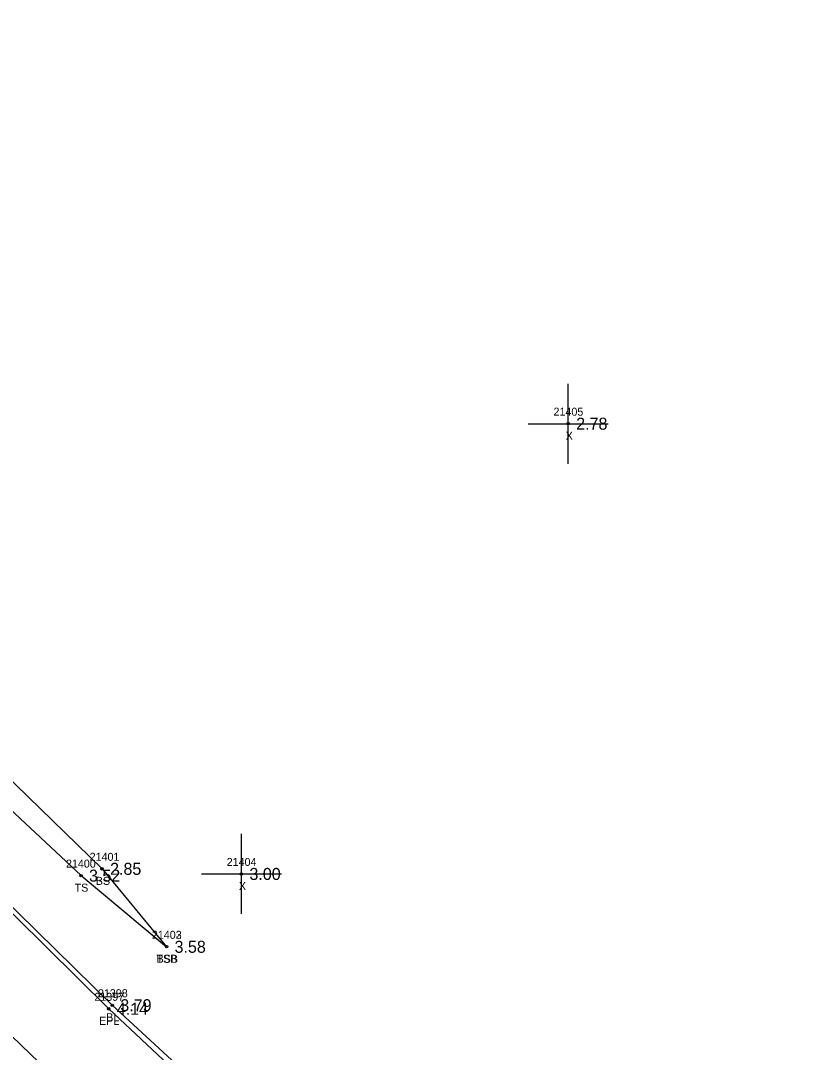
# Model space of a CAD drawing. Extents: x 2608745 to 2610333, y 641917 to 643463.
# Drawn here: x 2610075.3 to 2610174, y 642157.1 to 642286 of the extents above; entities that cross this region are included whole.
import ezdxf

# ---------------------------------------------------------------- set-up
doc = ezdxf.new("R2010")
doc.units = 0
for name, color, linetype in [('RD_DTM_BkLn1', 7, 'Continuous'), ('RD_DTM_BkLn2', 7, 'Continuous'), ('RD_DTM_BkLn_txCode', 7, 'Continuous'), ('RD_EX_Misc', 7, 'Continuous'), ('RD_EX_Misc_txCode', 7, 'Continuous'), ('RD_EX_Road', 7, 'Continuous'), ('RD_EX_Road_txCode', 7, 'Continuous'), ('RD_EX_TX_Misc_ELEV', 7, 'Continuous'), ('RD_EX_TX_Road_ELEV', 7, 'Continuous'), ('RD_SMD_Locator', 7, 'Continuous')]:
    doc.layers.add(name, color=color, linetype=linetype)

msp = doc.modelspace()

# ---------------------------------------------------------------- linework, layer by layer
at = {"layer": 'RD_DTM_BkLn1'}
for points in [[(2609568.4, 642647.43), (2609618.95, 642597.92), (2609693.89, 642525.38), (2609771.33, 642450.27), (2609850.26, 642373.69), (2609929.54, 642297.24), (2610000.01, 642230.49), (2610078.71, 642154.75), (2610156.09, 642080.44), (2610235.53, 642002.94), (2610263.59, 641975.77)], [(2609627.58, 642607.09), (2609630.23, 642605.37), (2609646.31, 642589.45), (2609703.16, 642535.02), (2609781.51, 642459.84), (2609859.44, 642383.51), (2609938.95, 642307.03), (2610008.76, 642239.49), (2610086.74, 642162.99), (2610105.31, 642145.89), (2610105.31, 642145.89), (2610140.26, 642113.1), (2610153.89, 642100.28), (2610164.72, 642089.82), (2610189.2, 642065.46)]]:
    msp.add_lwpolyline(points, dxfattribs=at)
at = {"layer": 'RD_DTM_BkLn2'}
for points in [[(2609582.66, 642657.54), (2609585.75, 642657.34), (2609622.53, 642623.2), (2609632.13, 642611.9), (2609647.4, 642591.36), (2609682.93, 642558.52), (2609706.14, 642537.77), (2609755.54, 642496.98), (2609786.05, 642464.88), (2609864.24, 642388.44), (2609941.53, 642310.67), (2610012.94, 642244.46), (2610082.83, 642179.18), (2610093.52, 642170.29)], [(2609755.54, 642496.98), (2609777.06, 642487.55), (2609794.23, 642472.67), (2609873.31, 642395.79), (2609950.73, 642318.92), (2610015.83, 642247.73), (2610085.46, 642180.03), (2610093.52, 642170.29)]]:
    msp.add_lwpolyline(points, dxfattribs=at)
at = {"layer": 'RD_EX_Misc'}
for p, q in [((2610143.72, 642230.64), (2610143.72, 642240.64)), ((2610138.72, 642235.64), (2610148.72, 642235.64)), ((2610102.88, 642174.39), (2610102.88, 642184.39)), ((2610097.88, 642179.39), (2610107.88, 642179.39))]:
    msp.add_line(p, q, dxfattribs=at)
at = {"layer": 'RD_EX_Road'}
msp.add_lwpolyline([(2609576.61, 642656.06), (2609590.88, 642642.24), (2609605.19, 642628.78), (2609627.58, 642607.09), (2609646.03, 642589.11), (2609702.18, 642534.04), (2609780.35, 642458.95), (2609858.79, 642382.83), (2609938.32, 642306.42), (2610008.62, 642239.32), (2610086.3, 642162.54), (2610164.18, 642089.49), (2610189.2, 642065.46), (2610214.78, 642040.19), (2610225.86, 642030.16), (2610226.32, 642028.39), (2610235.43, 642019.75), (2610260.23, 641995.63), (2610272.39, 641983.25)], dxfattribs=at)
at = {"layer": 'RD_SMD_Locator'}
for centre in [(2610143.72, 642235.64), (2610082.83, 642179.18), (2610085.46, 642180.03), (2610102.88, 642179.39), (2610093.52, 642170.29), (2610093.52, 642170.29), (2610086.3, 642162.54), (2610086.74, 642162.99)]:
    msp.add_circle(centre, 0.15, dxfattribs=at)

# ---------------------------------------------------------------- texts
at = {"layer": 'RD_DTM_BkLn_txCode'}
for s, p in [('21401', (2610083.91, 642181.03)), ('21400', (2610080.95, 642180.18)), ('BS', (2610084.68, 642178.03)), ('TS', (2610082.03, 642177.18)), ('21402', (2610091.69, 642171.29)), ('21403', (2610091.69, 642171.29)), ('TSB', (2610092.26, 642168.29)), ('BSB', (2610092.27, 642168.29)), ('21398', (2610084.95, 642163.99)), ('BL', (2610085.98, 642160.99))]:
    msp.add_text(s, height=1, dxfattribs=at).set_placement(p)
at = {"layer": 'RD_EX_Misc_txCode'}
for s, p in [('21405', (2610141.89, 642236.64)), ('X', (2610143.41, 642233.64)), ('21404', (2610101.04, 642180.39)), ('X', (2610102.56, 642177.39))]:
    msp.add_text(s, height=1, dxfattribs=at).set_placement(p)
at = {"layer": 'RD_EX_Road_txCode'}
for s, p in [('21397', (2610084.5, 642163.54)), ('EPL', (2610085.09, 642160.54))]:
    msp.add_text(s, height=1, dxfattribs=at).set_placement(p)
at = {"layer": 'RD_EX_TX_Misc_ELEV'}
for s, p in [('2.78', (2610144.72, 642234.89)), ('2.85', (2610086.46, 642179.28)), ('3.52', (2610083.83, 642178.43)), ('3.00', (2610103.88, 642178.64)), ('3.58', (2610094.52, 642169.54)), ('3.58', (2610094.52, 642169.54)), ('3.79', (2610087.74, 642162.24))]:
    msp.add_text(s, height=1.5, dxfattribs=at).set_placement(p)
at = {"layer": 'RD_EX_TX_Road_ELEV'}
msp.add_text('4.14', height=1.5, dxfattribs=at).set_placement((2610087.3, 642161.79))

doc.saveas('drawing.dxf')
